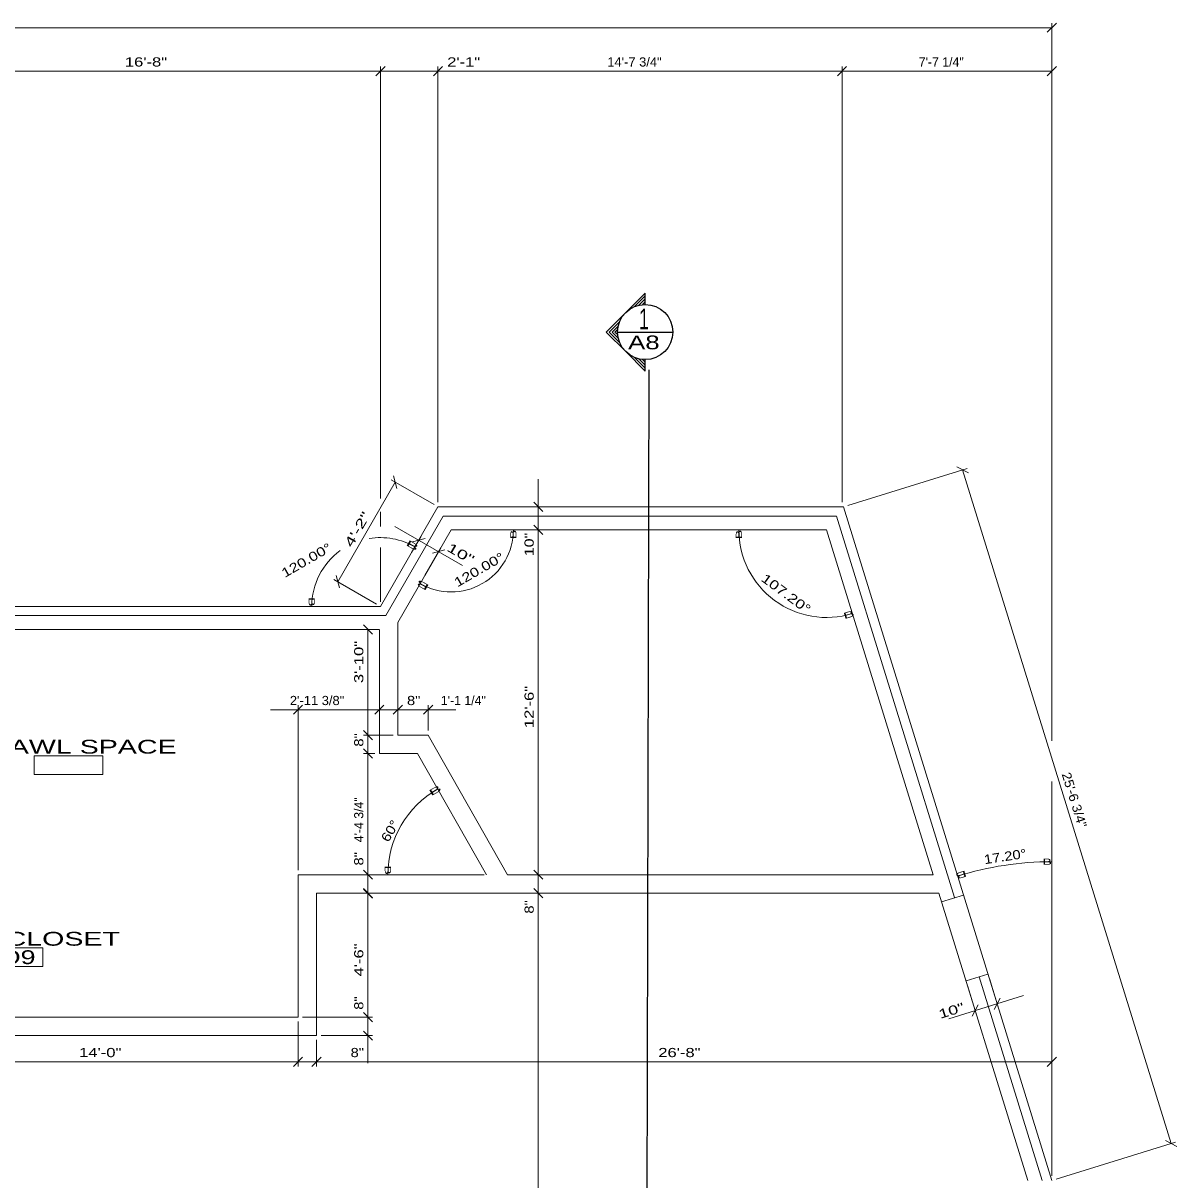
# Model space of a CAD drawing. Extents: x 7 to 126, y 6 to 93.
# Drawn here: x 83.75 to 125.58, y 51.09 to 93.02 of the extents above; entities that cross this region are included whole.
import ezdxf
from ezdxf.enums import TextEntityAlignment as Align

# ---------------------------------------------------------------- set-up
doc = ezdxf.new("R2010")
doc.units = 0
doc.header["$LTSCALE"] = 0.13
for name, color, linetype, lineweight in [('13', 7, 'Continuous', 13), ('14', 7, 'Continuous', 13), ('15', 7, 'Continuous', 13), ('40', 7, 'Continuous', 13), ('45', 7, 'Continuous', 13), ('50', 7, 'Continuous', 13), ('7', 7, 'Continuous', 13)]:
    doc.layers.add(name, color=color, linetype=linetype, lineweight=lineweight)

msp = doc.modelspace()

# ---------------------------------------------------------------- linework, layer by layer
at = {"layer": '13'}
for p, q in [((113.2426, 75.154), (117.5229, 61.3268)), ((120.6983, 51.0685), (118.4133, 58.4502))]:
    msp.add_line(p, q, dxfattribs=at)
msp.add_lwpolyline([(113.2426, 75.154), (98.9815, 75.154), (96.8981, 71.5456), (80.2315, 71.5456)], dxfattribs=at)
at = {"layer": '14'}
msp.add_line((113.4884, 75.4873), (121.0473, 51.0685), dxfattribs=at)
msp.add_lwpolyline([(113.4884, 75.4873), (98.789, 75.4873), (96.7057, 71.8789), (80.039, 71.8789), (75.039, 63.2187), (68.2977, 63.2187)], dxfattribs=at)
at = {"layer": '15'}
for p, q in [((112.874, 74.654), (116.7434, 62.154)), ((97.3312, 71.2956), (97.3312, 67.2122)), ((80.5729, 71.0456), (96.6563, 71.0456)), ((96.6645, 71.0456), (96.6645, 66.5456)), ((98.4324, 67.2122), (97.3312, 67.2122)), ((101.3135, 62.154), (98.4324, 67.2122)), ((98.0449, 66.5456), (96.6645, 66.5456)), ((100.5463, 62.154), (98.0449, 66.5456)), ((93.7139, 62.154), (93.7139, 56.9873)), ((93.7139, 62.154), (100.4688, 62.154)), ((116.7434, 62.154), (101.3135, 62.154)), ((94.3806, 61.4873), (94.3806, 56.3207)), ((116.9497, 61.4873), (94.3806, 61.4873)), ((120.1749, 51.0685), (116.9497, 61.4873)), ((117.0485, 61.1682), (117.8446, 61.4147)), ((118.7317, 58.5488), (117.9357, 58.3023)), ((93.7139, 56.9873), (79.7139, 56.9873)), ((94.3806, 56.3207), (79.7139, 56.3207))]:
    msp.add_line(p, q, dxfattribs=at)
msp.add_lwpolyline([(112.874, 74.654), (99.2702, 74.654), (97.3312, 71.2956)], dxfattribs=at)
at = {"layer": '40', "lineweight": 25}
for p, q in [((105.595, 82.53), (106.3021, 83.2371)), ((106.3021, 82.8229), (106.3021, 83.2371)), ((105.3021, 81.8229), (107.3021, 81.8229)), ((106.3021, 80.4087), (105.595, 81.1158)), ((106.3021, 80.4087), (106.3021, 80.8229)), ((106.4376, 80.4582), (106.3021, 30.3021))]:
    msp.add_line(p, q, dxfattribs=at)
at = {"layer": '40'}
for p, q in [((105.9167, 82.7457), (106.3021, 83.1311)), ((106.0735, 82.7964), (106.3021, 83.025)), ((106.2009, 82.8178), (106.3021, 82.9189)), ((106.3021, 80.5148), (105.9167, 80.9002)), ((106.3021, 80.6208), (106.0735, 80.8494)), ((106.3021, 80.7269), (106.2009, 80.8281))]:
    msp.add_line(p, q, dxfattribs=at)
at = {"layer": '40', "lineweight": 25}
msp.add_lwpolyline([(105.595, 81.1158), (104.8879, 81.8229), (105.595, 82.53)], dxfattribs=at)
at = {"layer": '40'}
for points in [[(105.3793, 81.4375), (104.9939, 81.8229), (105.3793, 82.2083)], [(105.3286, 81.5944), (105.1, 81.8229), (105.3286, 82.0515)], [(105.3072, 81.7218), (105.2061, 81.8229), (105.3072, 81.9241)]]:
    msp.add_lwpolyline(points, dxfattribs=at)
at = {"layer": '40', "lineweight": 25}
msp.add_circle((106.3021, 81.8229), 1, dxfattribs=at)
at = {"layer": '45'}
for points in [[(84.1456, 65.7892), (86.6308, 65.7892), (86.6308, 66.4598), (84.1456, 66.4598)], [(81.9754, 58.8277), (84.4605, 58.8277), (84.4605, 59.4984), (81.9754, 59.4984)]]:
    msp.add_lwpolyline(points, close=True, dxfattribs=at)
at = {"layer": '50'}
for p, q in [((121.0473, 92.8542), (16.7057, 92.8542)), ((121.2139, 93.0208), (120.8806, 92.6875)), ((121.0473, 93.0208), (121.0473, 67.0104)), ((121.0473, 92.8542), (121.0473, 91.1146)), ((96.8724, 91.4479), (96.539, 91.1146)), ((96.8724, 91.4479), (96.539, 91.1146)), ((96.7057, 91.4479), (96.7057, 75.7917)), ((98.6224, 91.1146), (98.9557, 91.4479)), ((98.6224, 91.1146), (98.9557, 91.4479)), ((98.789, 75.654), (98.789, 91.4479)), ((113.6051, 91.4479), (113.2718, 91.1146)), ((113.2718, 91.1146), (113.6051, 91.4479)), ((113.2718, 91.1146), (113.6051, 91.4479)), ((113.4384, 75.654), (113.4384, 91.4479)), ((121.2139, 91.4479), (120.8806, 91.1146)), ((80.039, 91.2812), (96.7057, 91.2812)), ((95.7057, 91.2812), (99.789, 91.2812)), ((98.789, 91.2812), (113.4384, 91.2812)), ((113.4384, 91.2812), (121.0473, 91.2812)), ((113.4384, 91.2812), (113.4384, 91.1146)), ((113.6476, 75.5366), (117.9725, 76.8754)), ((117.6048, 76.9361), (118.0218, 76.7162)), ((117.8133, 76.8261), (125.3721, 52.4073)), ((97.238, 76.3828), (95.1546, 72.7744)), ((98.6447, 75.5707), (97.0936, 76.4662)), ((97.177, 76.6105), (97.299, 76.1552)), ((102.4271, 73.654), (102.4271, 76.4873)), ((102.5938, 75.3207), (102.2604, 75.654)), ((105.972, 75.4873), (102.2604, 75.4873)), ((96.7057, 74.7708), (96.7057, 75.3021)), ((99.68, 73.3639), (97.2263, 74.7806)), ((102.2604, 74.8207), (102.5938, 74.4873)), ((102.2604, 74.8207), (102.5938, 74.4873)), ((105.9054, 74.654), (102.2604, 74.654)), ((102.4271, 74.654), (102.4271, 62.154)), ((97.8307, 73.8275), (98.1756, 74.4249)), ((98.32, 74.3416), (97.8646, 74.2196)), ((96.7057, 72.0456), (96.7057, 74.0104)), ((98.3118, 72.9941), (98.8973, 74.0082)), ((98.5863, 73.8029), (99.0416, 73.9249)), ((95.2157, 72.5467), (95.0936, 73.0021)), ((96.5614, 71.9622), (95.0103, 72.8577)), ((96.0833, 71.2122), (96.4167, 70.8789)), ((96.4896, 71.0456), (96.0833, 71.0456)), ((96.25, 67.2122), (96.25, 71.0456)), ((96.6645, 68.6289), (96.6645, 67.9688)), ((92.7139, 68.1354), (97.6645, 68.1354)), ((93.8806, 68.3021), (93.5473, 67.9688)), ((93.7139, 62.3207), (93.7139, 68.3021)), ((95.6645, 68.1354), (98.3312, 68.1354)), ((96.25, 65.5456), (96.25, 68.2122)), ((96.3312, 68.1354), (99.4324, 68.1354)), ((96.4978, 67.9688), (96.8312, 68.3021)), ((96.8312, 68.3021), (96.4978, 67.9688)), ((97.1645, 67.9688), (97.4978, 68.3021)), ((97.4978, 68.3021), (97.1645, 67.9688)), ((97.3312, 67.3789), (97.3312, 68.3021)), ((98.2657, 67.9688), (98.599, 68.3021)), ((98.4324, 67.3789), (98.4324, 68.3021)), ((96.4167, 67.0456), (96.0833, 67.3789)), ((96.4167, 67.0456), (96.0833, 67.3789)), ((97.1645, 67.2122), (96.0833, 67.2122)), ((96.0833, 66.7122), (96.4167, 66.3789)), ((96.0833, 66.7122), (96.4167, 66.3789)), ((96.0833, 66.7122), (96.4167, 66.3789)), ((96.4978, 66.5456), (96.0833, 66.5456)), ((96.25, 62.154), (96.25, 66.5456)), ((96.25, 66.5456), (96.4167, 66.5456)), ((121.0473, 51.2352), (121.0473, 65.5312)), ((96.25, 60.4873), (96.25, 63.154)), ((102.4271, 60.4873), (102.4271, 63.154)), ((96.4167, 61.9873), (96.0833, 62.3207)), ((96.4167, 61.9873), (96.0833, 62.3207)), ((96.9247, 62.154), (96.0833, 62.154)), ((102.5938, 61.9873), (102.2604, 62.3207)), ((102.5938, 61.9873), (102.2604, 62.3207)), ((105.062, 62.154), (102.2604, 62.154)), ((96.0833, 61.654), (96.4167, 61.3207)), ((96.4167, 61.3021), (96.0833, 61.6354)), ((102.2604, 61.654), (102.5938, 61.3207)), ((102.2604, 61.654), (102.5938, 61.3207)), ((94.5473, 61.4873), (96.4167, 61.4873)), ((95.6486, 61.4873), (96.4167, 61.4873)), ((96.25, 61.4873), (96.25, 56.9873)), ((105.4985, 61.4873), (102.2604, 61.4873)), ((102.4271, 61.4873), (102.4271, 35.1845)), ((118.781, 58.3896), (119.113, 57.3172)), ((96.25, 55.3207), (96.25, 57.9873)), ((117.9849, 58.1431), (118.3169, 57.0708)), ((120.019, 57.7721), (117.3123, 56.9343)), ((118.9537, 57.2679), (119.1736, 57.6849)), ((96.4167, 56.8207), (96.0833, 57.154)), ((96.4167, 56.8207), (96.0833, 57.154)), ((118.3775, 57.4385), (118.1577, 57.0215)), ((93.7139, 56.8369), (93.7139, 55.2083)), ((93.8806, 56.9873), (96.4167, 56.9873)), ((94.5473, 56.3207), (96.4167, 56.3207)), ((96.0833, 56.4873), (96.4167, 56.154)), ((94.3806, 56.1703), (94.3806, 55.2083)), ((93.7139, 55.375), (79.7139, 55.375)), ((92.7139, 55.375), (95.3806, 55.375)), ((93.8806, 55.5417), (93.5473, 55.2083)), ((93.8806, 55.5417), (93.5473, 55.2083)), ((93.8806, 55.5417), (93.5473, 55.2083)), ((93.7139, 55.375), (93.7139, 55.5417)), ((94.2139, 55.2083), (94.5473, 55.5417)), ((94.2139, 55.2083), (94.5473, 55.5417)), ((121.0473, 55.375), (94.3806, 55.375)), ((121.2139, 55.5417), (120.8806, 55.2083)), ((121.0473, 51.4019), (121.0473, 55.5417)), ((121.2065, 51.1178), (125.5314, 52.4566)), ((125.5806, 52.2974), (125.1636, 52.5172))]:
    msp.add_line(p, q, dxfattribs=at)
for centre, radius, start, end in [((99.2702, 74.654), 2.252, 240.00035, 0), ((112.874, 74.654), 3.1755, 180, 287.20002), ((96.7057, 71.8789), 2.4937, 59.99981, 99.54345), ((96.7057, 71.8789), 2.4937, 125.87333, 180), ((100.5463, 62.154), 3.5747, 119.66553, 180), ((121.0473, 51.0685), 11.555, 90, 107.19996)]:
    msp.add_arc(centre, radius, start, end, dxfattribs=at)
at = {"layer": '7'}
msp.add_lwpolyline([(115.8724, 34.3511), (77.539, 34.3511), (75.8724, 37.2379), (59.2057, 37.2379), (57.539, 34.3511), (40.8724, 34.3511), (16.7057, 76.209), (22.539, 86.3127), (34.2057, 86.3127), (44.2057, 68.9922), (60.8724, 68.9922), (64.2057, 63.2187), (65.039, 63.2187), (75.039, 63.2187), (80.039, 71.8789), (96.7057, 71.8789), (98.789, 75.4873), (113.4884, 75.4873), (121.0473, 51.0685)], dxfattribs=at)

# ---------------------------------------------------------------- texts
at = {"layer": '40'}
for s, height, width, p in [('1', 0.75, 0.65, (106.2583, 81.924)), ('A8 ', 0.5, 1.4, (106.3844, 81.1979))]:
    msp.add_text(s, height=height, dxfattribs=dict(at, width=width)).set_placement(p, align=Align.CENTER)
at = {"layer": '45'}
for s, width, p in [('     CRAWL SPACE    ', 1.55, (85.3956, 66.5432)), ('    CEDAR CLOSET    ', 1.55, (83.2254, 59.5817)), (' BO9 ', 1.45, (83.2253, 58.915))]:
    msp.add_text(s, height=0.5, dxfattribs=dict(at, width=width)).set_placement(p, align=Align.CENTER)
at = {"layer": '50'}
for s, width, p in [('16\'-8"', 1.35, (87.4354, 91.4479)), ('2\'-1"', 1.35, (99.1224, 91.4479)), ('14\'-7 3/4"', 1.05, (104.9274, 91.4479)), ('2\'-11 3/8"', 1.05, (93.4179, 68.3021)), ('8"', 1.2, (97.6645, 68.3021)), ('14\'-0"', 1.35, (85.7769, 55.5417)), ('8"', 1.2, (95.62, 55.5417)), ('26\'-8"', 1.35, (106.7769, 55.5417))]:
    msp.add_text(s, height=0.3333, dxfattribs=dict(at, width=width)).set_placement(p)
for s, p in [('7\'-7 1/4"', (116.2219, 91.4479)), ('1\'-1 1/4"', (98.8917, 68.3021))]:
    msp.add_text(s, height=0.3333, dxfattribs=at).set_placement(p)
for s, rotation, width, p in [('4\'-2"', 60, 1.55, (95.6661, 73.9937)), ('10"', 90, 1.3, (102.2604, 73.6982)), ('120.00°', 30, 1.3, (93.2337, 72.9084)), ('10"', 330, 1.6, (99.0757, 73.9159)), ('120.00°', 30, 1.3, (99.4958, 72.5677)), ('107.20°', 323.6, 1.35, (110.4766, 72.8254)), ('3\'-10"', 90, 1.35, (96.0833, 69.0981)), ('12\'-6"', 90, 1.35, (102.2604, 67.467)), ('8"', 90, 1.2, (96.0833, 66.7956)), ('25\'-6 3/4"', 287.2, 1.1, (121.4011, 65.7993)), ('60°', 59.833, 1.2, (96.9917, 63.3088)), ('8"', 90, 1.2, (96.0833, 62.4873)), ('17.20°', 8.6, 1.2, (118.615, 62.5348)), ('8"', 90, 1.2, (102.2604, 60.7431)), ('4\'-6"', 90, 1.35, (96.0833, 58.4657)), ('8"', 90, 1.2, (96.0833, 57.2582)), ('10"', 17.199, 1.45, (117.0029, 56.9295))]:
    msp.add_text(s, height=0.3333, rotation=rotation, dxfattribs=dict(at, width=width)).set_placement(p)
for rotation, width, p in [(330, 2.35, (98.0081, 73.8781)), (90, 1.7, (101.6332, 74.654)), (90, 1.7, (109.8096, 74.654)), (150, 2.35, (98.0886, 72.8641)), (270, 1.7, (94.1009, 71.8789)), (17.2, 2.05, (113.9116, 71.5347)), (29.666, 2.35, (98.942, 65.2263)), (270, 1.7, (96.8604, 62.154)), (197.2, 2.05, (117.5318, 62.1926))]:
    msp.add_text('B', height=0.2222, rotation=rotation, dxfattribs=dict(at, width=width)).set_placement(p, align=Align.RIGHT)
msp.add_text('4\'-4 3/4"', height=0.3333, rotation=90, dxfattribs=at).set_placement((96.0833, 63.3288))
at = {"layer": '50', "width": 1.7}
msp.add_text('B', height=0.2222, dxfattribs=at).set_placement((121.0473, 62.5124), align=Align.RIGHT)

doc.saveas('drawing.dxf')
